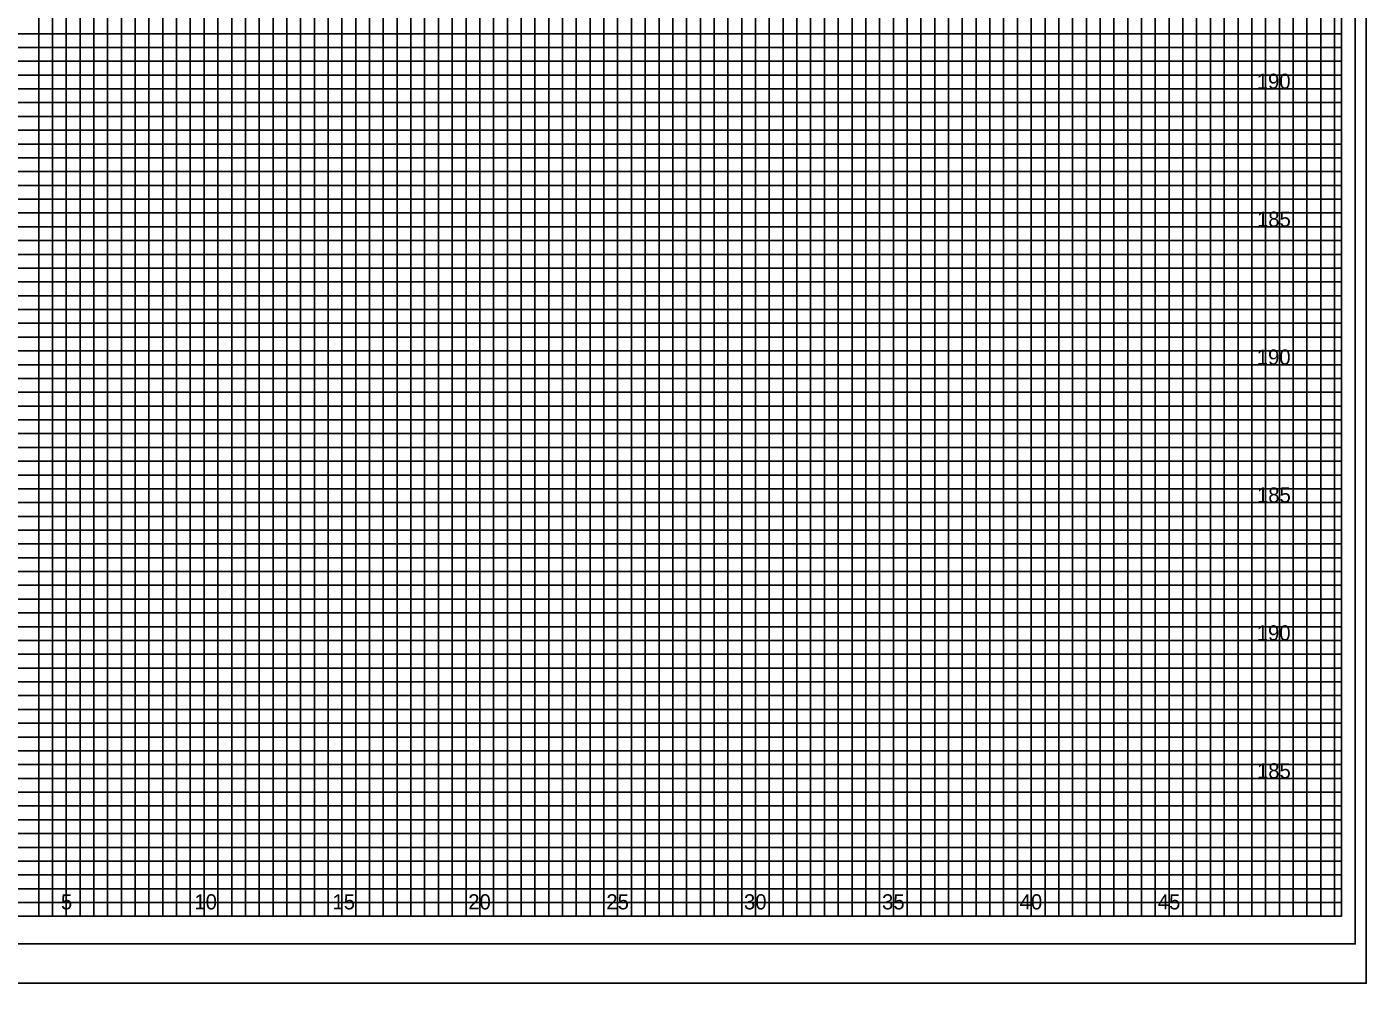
# Model space of a CAD drawing. Extents: x -4 to 103, y -2 to 67.
# Drawn here: x 54.82 to 103.4, y -2.43 to 32.25 of the extents above; entities that cross this region are included whole.
import ezdxf

# ---------------------------------------------------------------- set-up
doc = ezdxf.new("R2010")
doc.units = 0
for name, color, linetype in [('Exist XS Ground Line', 7, 'Continuous'), ('Old_Level_10', 7, 'Continuous'), ('Old_Level_16', 7, 'Continuous'), ('Old_Level_3', 7, 'Continuous'), ('Old_Level_4', 7, 'Continuous'), ('Old_Level_5', 7, 'Continuous'), ('Old_Level_8', 7, 'Continuous'), ('Prop XS Elevation Labels', 7, 'Continuous'), ('Prop XS Finish Grade Concrete', 7, 'Continuous')]:
    doc.layers.add(name, color=color, linetype=linetype)

msp = doc.modelspace()

# ---------------------------------------------------------------- linework, layer by layer
at = {"layer": 'Exist XS Ground Line'}
msp.add_lwpolyline([(102.5, 65), (0, 65), (0, 0), (102.5, 0)], close=True, dxfattribs=at)
at = {"layer": 'Old_Level_10'}
for p, q in [((56.25, 0), (56.25, 65)), ((58.75, 0), (58.75, 65)), ((61.25, 0), (61.25, 65)), ((63.75, 0), (63.75, 65)), ((66.25, 0), (66.25, 65)), ((68.75, 0), (68.75, 65)), ((71.25, 0), (71.25, 65)), ((73.75, 0), (73.75, 65)), ((91.25, 0), (91.25, 63.425)), ((93.75, 0), (93.75, 63.425)), ((96.25, 0), (96.25, 63.425)), ((98.75, 0), (98.75, 63.425)), ((101.25, 0), (101.25, 63.425)), ((76.25, 0), (76.25, 62)), ((78.75, 0), (78.75, 62)), ((81.25, 0), (81.25, 62)), ((83.75, 0), (83.75, 62)), ((86.25, 0), (86.25, 62)), ((88.75, 0), (88.75, 62)), ((0, 30), (102.5, 30)), ((0, 27.5), (102.5, 27.5)), ((0, 25), (102.5, 25)), ((0, 22.5), (102.5, 22.5)), ((0, 20), (102.5, 20)), ((0, 17.5), (102.5, 17.5)), ((0, 15), (102.5, 15)), ((0, 12.5), (102.5, 12.5)), ((0, 10), (102.5, 10)), ((0, 7.5), (102.5, 7.5)), ((0, 5), (102.5, 5)), ((0, 2.5), (102.5, 2.5))]:
    msp.add_line(p, q, dxfattribs=at)
at = {"layer": 'Old_Level_3'}
msp.add_line((-3.5, -2.425), (103.4, -2.425), dxfattribs=at)
at = {"layer": 'Old_Level_4'}
msp.add_lwpolyline([(103, 66), (-2.8, 66), (-2.8, -1), (103, -1)], close=True, dxfattribs=at)
at = {"layer": 'Old_Level_5'}
msp.add_lwpolyline([(103.4, 67.4), (-3.5, 67.4), (-3.5, -2.425), (103.4, -2.425)], close=True, dxfattribs=at)
at = {"layer": 'Old_Level_8'}
for points in [[(56.25, 0), (56.25, 65)], [(58.75, 65), (58.75, 0), (61.25, 0), (61.25, 65)], [(63.75, 65), (63.75, 0), (66.25, 0), (66.25, 65)], [(68.75, 65), (68.75, 0), (71.25, 0), (71.25, 65)], [(73.75, 65), (73.75, 0), (76.25, 0), (76.25, 62)], [(88.75, 62), (88.75, 0), (91.25, 0), (91.25, 63.425)], [(93.75, 63.425), (93.75, 0), (96.25, 0), (96.25, 63.425)], [(98.75, 63.425), (98.75, 0), (101.25, 0), (101.25, 63.425)], [(78.75, 62), (78.75, 0), (81.25, 0), (81.25, 62)], [(83.75, 62), (83.75, 0), (86.25, 0), (86.25, 62)], [(0, 27.5), (102.5, 27.5), (102.5, 30), (0, 30)], [(0, 22.5), (102.5, 22.5), (102.5, 25), (0, 25)], [(0, 17.5), (102.5, 17.5), (102.5, 20), (0, 20)], [(0, 12.5), (102.5, 12.5), (102.5, 15), (0, 15)], [(0, 7.5), (102.5, 7.5), (102.5, 10), (0, 10)], [(0, 2.5), (102.5, 2.5), (102.5, 5), (0, 5)]]:
    msp.add_lwpolyline(points, dxfattribs=at)
at = {"layer": 'Prop XS Elevation Labels'}
for points in [[(54.75, 0), (55.25, 0), (55.25, 65)], [(55.75, 65), (55.75, 0), (56.75, 0), (56.75, 65)], [(57.25, 65), (57.25, 0), (57.75, 0), (57.75, 65)], [(58.25, 65), (58.25, 0), (59.25, 0), (59.25, 65)], [(59.75, 65), (59.75, 0), (60.25, 0), (60.25, 65)], [(60.75, 65), (60.75, 0), (61.75, 0), (61.75, 65)], [(62.25, 65), (62.25, 0), (62.75, 0), (62.75, 65)], [(63.25, 65), (63.25, 0), (64.25, 0), (64.25, 65)], [(64.75, 65), (64.75, 0), (65.25, 0), (65.25, 65)], [(65.75, 65), (65.75, 0), (66.75, 0), (66.75, 65)], [(67.25, 65), (67.25, 0), (67.75, 0), (67.75, 65)], [(68.25, 65), (68.25, 0), (69.25, 0), (69.25, 65)], [(69.75, 65), (69.75, 0), (70.25, 0), (70.25, 65)], [(70.75, 65), (70.75, 0), (71.75, 0), (71.75, 65)], [(72.25, 65), (72.25, 0), (72.75, 0), (72.75, 65)], [(73.25, 65), (73.25, 0), (74.25, 0), (74.25, 62)], [(89.75, 62), (89.75, 0), (90.25, 0), (90.25, 63.425)], [(90.75, 63.425), (90.75, 0), (91.75, 0), (91.75, 63.425)], [(92.25, 63.425), (92.25, 0), (92.75, 0), (92.75, 63.425)], [(93.25, 63.425), (93.25, 0), (94.25, 0), (94.25, 63.425)], [(94.75, 63.425), (94.75, 0), (95.25, 0), (95.25, 63.425)], [(95.75, 63.425), (95.75, 0), (96.75, 0), (96.75, 63.425)], [(97.25, 63.425), (97.25, 0), (97.75, 0), (97.75, 63.425)], [(98.25, 63.425), (98.25, 0), (99.25, 0), (99.25, 63.425)], [(99.75, 63.425), (99.75, 0), (100.25, 0), (100.25, 63.425)], [(100.25, 63.425), (100.75, 63.425), (100.75, 0), (101.75, 0), (101.75, 63.425), (102.25, 63.425), (102.25, 0)], [(74.75, 62), (74.75, 0), (75.25, 0), (75.25, 62)], [(75.75, 62), (75.75, 0), (76.75, 0), (76.75, 62)], [(77.25, 62), (77.25, 0), (77.75, 0), (77.75, 62)], [(78.25, 62), (78.25, 0), (79.25, 0), (79.25, 62)], [(79.75, 62), (79.75, 0), (80.25, 0), (80.25, 62)], [(80.75, 62), (80.75, 0), (81.75, 0), (81.75, 62)], [(82.25, 62), (82.25, 0), (82.75, 0), (82.75, 62)], [(83.25, 62), (83.25, 0), (84.25, 0), (84.25, 62)], [(84.75, 62), (84.75, 0), (85.25, 0), (85.25, 62)], [(85.75, 62), (85.75, 0), (86.75, 0), (86.75, 62)], [(87.25, 62), (87.25, 0), (87.75, 0), (87.75, 62)], [(88.25, 62), (88.25, 0), (89.25, 0), (89.25, 62)], [(0, 31.5), (102.5, 31.5), (102.5, 32), (0, 32)], [(0, 30.5), (102.5, 30.5), (102.5, 31), (0, 31)], [(0, 29), (102.5, 29), (102.5, 29.5), (0, 29.5)], [(0, 28), (102.5, 28), (102.5, 28.5), (0, 28.5)], [(0, 26.5), (102.5, 26.5), (102.5, 27), (0, 27)], [(0, 25.5), (102.5, 25.5), (102.5, 26), (0, 26)], [(0, 24), (102.5, 24), (102.5, 24.5), (0, 24.5)], [(0, 23), (102.5, 23), (102.5, 23.5), (0, 23.5)], [(0, 21.5), (102.5, 21.5), (102.5, 22), (0, 22)], [(0, 20.5), (102.5, 20.5), (102.5, 21), (0, 21)], [(0, 19), (102.5, 19), (102.5, 19.5), (0, 19.5)], [(0, 18), (102.5, 18), (102.5, 18.5), (0, 18.5)], [(0, 16.5), (102.5, 16.5), (102.5, 17), (0, 17)], [(0, 15.5), (102.5, 15.5), (102.5, 16), (0, 16)], [(0, 14), (102.5, 14), (102.5, 14.5), (0, 14.5)], [(0, 13), (102.5, 13), (102.5, 13.5), (0, 13.5)], [(0, 11.5), (102.5, 11.5), (102.5, 12), (0, 12)], [(0, 10.5), (102.5, 10.5), (102.5, 11), (0, 11)], [(0, 9), (102.5, 9), (102.5, 9.5), (0, 9.5)], [(0, 8), (102.5, 8), (102.5, 8.5), (0, 8.5)], [(0, 6.5), (102.5, 6.5), (102.5, 7), (0, 7)], [(0, 5.5), (102.5, 5.5), (102.5, 6), (0, 6)], [(0, 4), (102.5, 4), (102.5, 4.5), (0, 4.5)], [(0, 3), (102.5, 3), (102.5, 3.5), (0, 3.5)], [(0, 1.5), (102.5, 1.5), (102.5, 2), (0, 2)], [(0, 0.5), (102.5, 0.5), (102.5, 1), (0, 1)]]:
    msp.add_lwpolyline(points, dxfattribs=at)

# ---------------------------------------------------------------- texts
at = {"layer": 'Old_Level_16'}
for s, p in [('5', (56.0574, 0.25)), ('10', (60.8971, 0.25)), ('15', (65.9057, 0.25)), ('20', (70.8312, 0.25)), ('25', (75.8399, 0.25)), ('30', (80.8312, 0.25)), ('35', (85.8399, 0.25)), ('40', (90.8313, 0.25)), ('45', (95.8399, 0.25))]:
    msp.add_text(s, height=0.55, dxfattribs=at).set_placement(p)
at = {"layer": 'Prop XS Finish Grade Concrete'}
for s, p in [('190', (99.4296, 30)), ('185', (99.4383, 25)), ('190', (99.4296, 20)), ('185', (99.4383, 15)), ('190', (99.4296, 10)), ('185', (99.4383, 5))]:
    msp.add_text(s, height=0.55, dxfattribs=at).set_placement(p)

doc.saveas('drawing.dxf')
